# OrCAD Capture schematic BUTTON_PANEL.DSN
size B
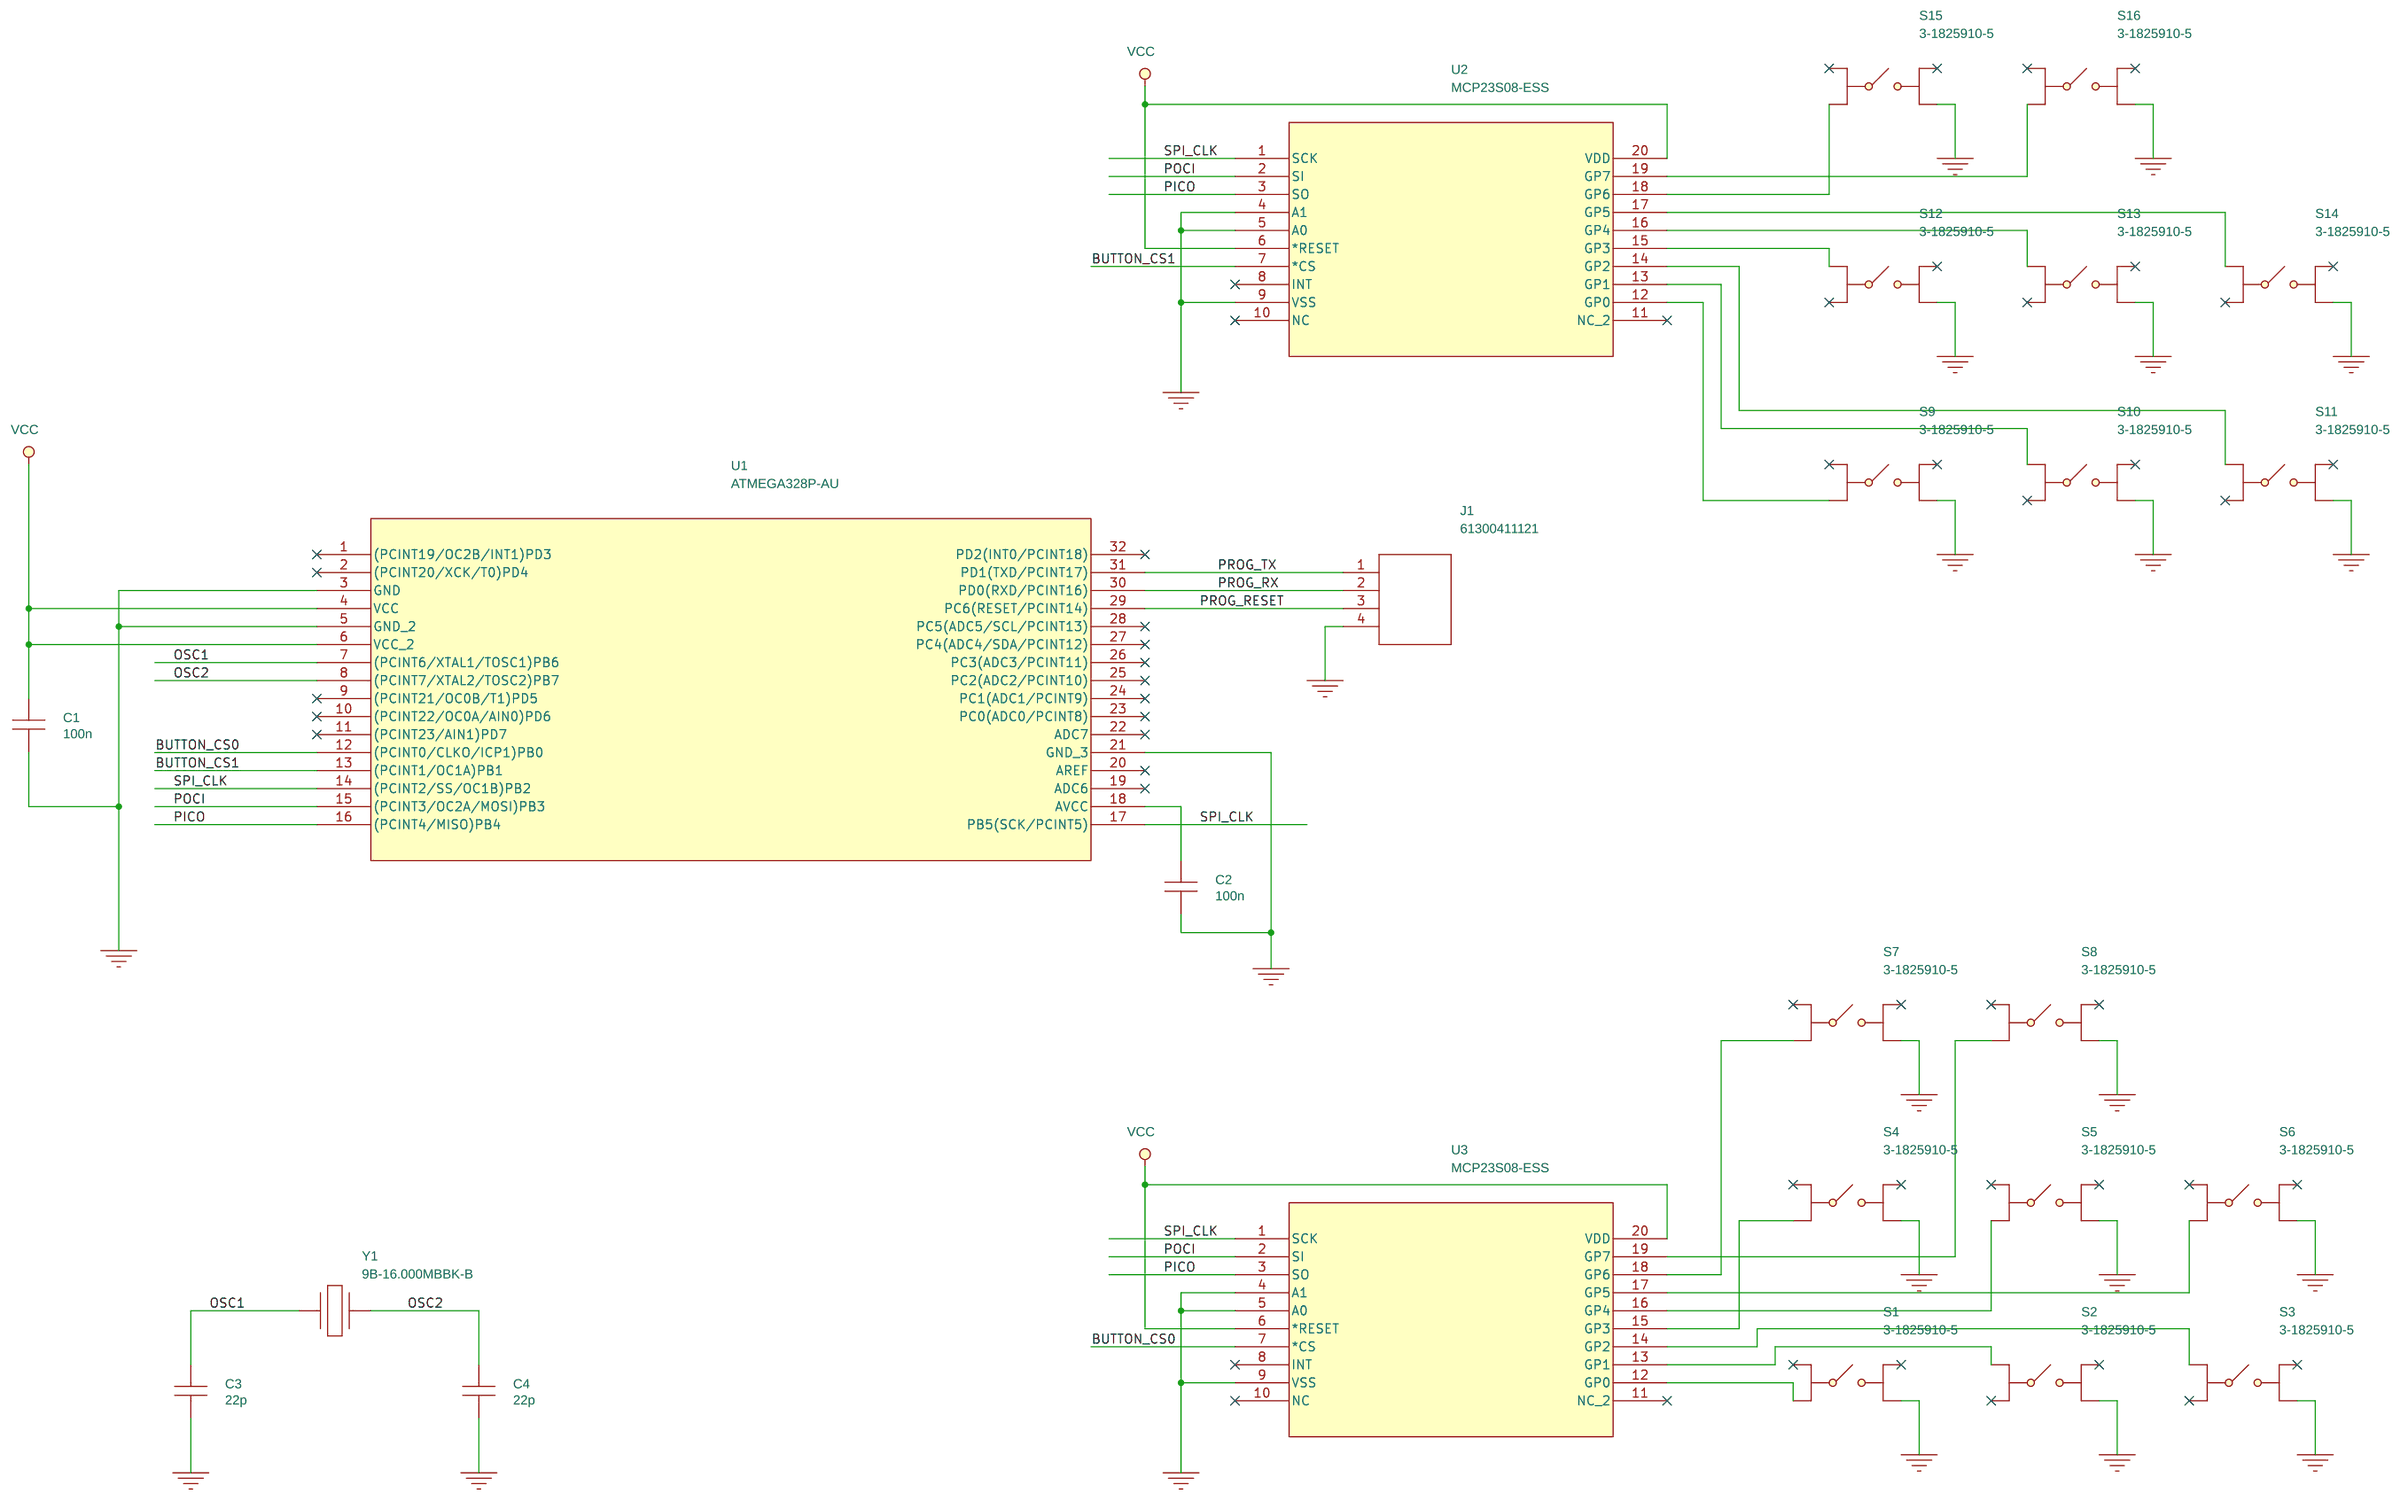
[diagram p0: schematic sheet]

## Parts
C1  100n  [SMC0603]
C2  100n  [SMC0603]
C3  22p  [SMC0603]
C4  22p  [SMC0603]
J1  61300411121  [HDRV4W95P0X254_1X4_1016X254X854P]
S1  3-1825910-5  [318259105]
S2  3-1825910-5  [318259105]
S3  3-1825910-5  [318259105]
S4  3-1825910-5  [318259105]
S5  3-1825910-5  [318259105]
S6  3-1825910-5  [318259105]
S7  3-1825910-5  [318259105]
S8  3-1825910-5  [318259105]
S9  3-1825910-5  [318259105]
S10  3-1825910-5  [318259105]
S11  3-1825910-5  [318259105]
S12  3-1825910-5  [318259105]
S13  3-1825910-5  [318259105]
S14  3-1825910-5  [318259105]
S15  3-1825910-5  [318259105]
S16  3-1825910-5  [318259105]
U1  ATMEGA328P-AU  [32A_MCH]
U2  MCP23S08-ESS  [SSOP20_MC_MCH]
U3  MCP23S08-ESS  [SSOP20_MC_MCH]
Y1  9B-16.000MBBK-B  [9B16000MBBKB]

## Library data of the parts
C1 C2 = CAP_NP: Manufacturer Name: KYOCERA AVX; Manufacturer Part Number: KGM15BR71H104JT; Manufacturer_Part_Number: KGM15BR71H104JT; Mfr_Name: KYOCERA AVX; Part Number: KGM15BR71H104JT
C3 C4 = CAP_NP
J1 = 61300411121: Manufacturer Name: W眉rth Elektronik; Source Id: SamacSys
S1-S16 = 3-1825910-5_0: Manufacturer Name: TE Connectivity; Source Id: SamacSys
U1 = ATMEGA328PB-ANR: Manufacturer Name: Microchip; Source Id: UL
U2 U3 = MCP23S08T-ESS: Manufacturer Name: Microchip; Manufacturer Part Number: MCP23S08T-E/SS; Part Number: MCP23S08T-E/SS; Source Id: UL
Y1 = 9B-16_0.000MBBK-B: Manufacturer Name: TXC CORPORATION; Source Id: SamacSys

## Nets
VCC: C1.1 U1.4(VCC) U1.6(VCC_2) U2.6(*RESET) U2.20(VDD) U3.6(*RESET) U3.20(VDD)
0: C1.2 C2.2 C3.2 C4.2 J1.4 S1.4(NO_2) S2.4(NO_2) S3.4(NO_2) S4.4(NO_2) S5.4(NO_2) S6.4(NO_2) S7.4(NO_2) S8.4(NO_2) S9.4(NO_2) S10.4(NO_2) S11.4(NO_2) S12.4(NO_2) S13.4(NO_2) S14.4(NO_2) S15.4(NO_2) S16.4(NO_2) U1.3(GND) U1.5(GND_2) U1.21(GND_3) U2.4(A1) U2.5(A0) U2.9(VSS) U3.4(A1) U3.5(A0) U3.9(VSS)
BUTTON_CS0: U1.12((PCINT0/CLKO/ICP1)PB0) U3.7(*CS)
BUTTON_CS1: U1.13((PCINT1/OC1A)PB1) U2.7(*CS)
OSC1: C3.1 U1.7((PCINT6/XTAL1/TOSC1)PB6) Y1.2
OSC2: C4.1 U1.8((PCINT7/XTAL2/TOSC2)PB7) Y1.1
PICO: U1.16((PCINT4/MISO)PB4) U2.3(SO) U3.3(SO)
POCI: U1.15((PCINT3/OC2A/MOSI)PB3) U2.2(SI) U3.2(SI)
PROG_RESET: J1.3 U1.29(PC6(RESET/PCINT14))
PROG_RX: J1.2 U1.30(PD0(RXD/PCINT16))
PROG_TX: J1.1 U1.31(PD1(TXD/PCINT17))
SPI_CLK: U1.14((PCINT2/SS/OC1B)PB2) U1.17(PB5(SCK/PCINT5)) U2.1(SCK) U3.1(SCK)
N02377: C2.1 U1.18(AVCC)
N05794: S1.2(COM) U3.12(GP0)
N05801: S2.1(COM) U3.13(GP1)
N05819: S3.1(COM) U3.14(GP2)
N05837: S4.2(COM) U3.15(GP3)
N05849: S5.2(COM) U3.16(GP4)
N05856: S6.2(COM) U3.17(GP5)
N05863: S7.2(COM) U3.18(GP6)
N05875: S8.2(COM) U3.19(GP7)
N08201: S9.2(COM) U2.12(GP0)
N08213: S10.1(COM) U2.13(GP1)
N08231: S11.1(COM) U2.14(GP2)
N08249: S12.1(COM) U2.15(GP3)
N08256: S13.1(COM) U2.16(GP4)
N08263: S14.1(COM) U2.17(GP5)
N08270: S15.2(COM) U2.18(GP6)
N08277: S16.2(COM) U2.19(GP7)

Not connected (* = marked no-connect by the designer): S1 1(COM)* 3(NO_1)*; S2 2(COM)* 3(NO_1)*; S3 2(COM)* 3(NO_1)*; S4 1(COM)* 3(NO_1)*; S5 1(COM)* 3(NO_1)*; S6 1(COM)* 3(NO_1)*; S7 1(COM)* 3(NO_1)*; S8 1(COM)* 3(NO_1)*; S9 1(COM)* 3(NO_1)*; S10 2(COM)* 3(NO_1)*; S11 2(COM)* 3(NO_1)*; S12 2(COM)* 3(NO_1)*; S13 2(COM)* 3(NO_1)*; S14 2(COM)* 3(NO_1)*; S15 1(COM)* 3(NO_1)*; S16 1(COM)* 3(NO_1)*; U1 1((PCINT19/OC2B/INT1)PD3)* 2((PCINT20/XCK/T0)PD4)* 9((PCINT21/OC0B/T1)PD5)* 10((PCINT22/OC0A/AIN0)PD6)* 11((PCINT23/AIN1)PD7)* 19(ADC6)* 20(AREF)* 22(ADC7)* 23(PC0(ADC0/PCINT8))* 24(PC1(ADC1/PCINT9))* 25(PC2(ADC2/PCINT10))* 26(PC3(ADC3/PCINT11))* 27(PC4(ADC4/SDA/PCINT12))* 28(PC5(ADC5/SCL/PCINT13))* 32(PD2(INT0/PCINT18))*; U2 8(INT)* 10(NC)* 11(NC_2)*; U3 8(INT)* 10(NC)* 11(NC_2)*
